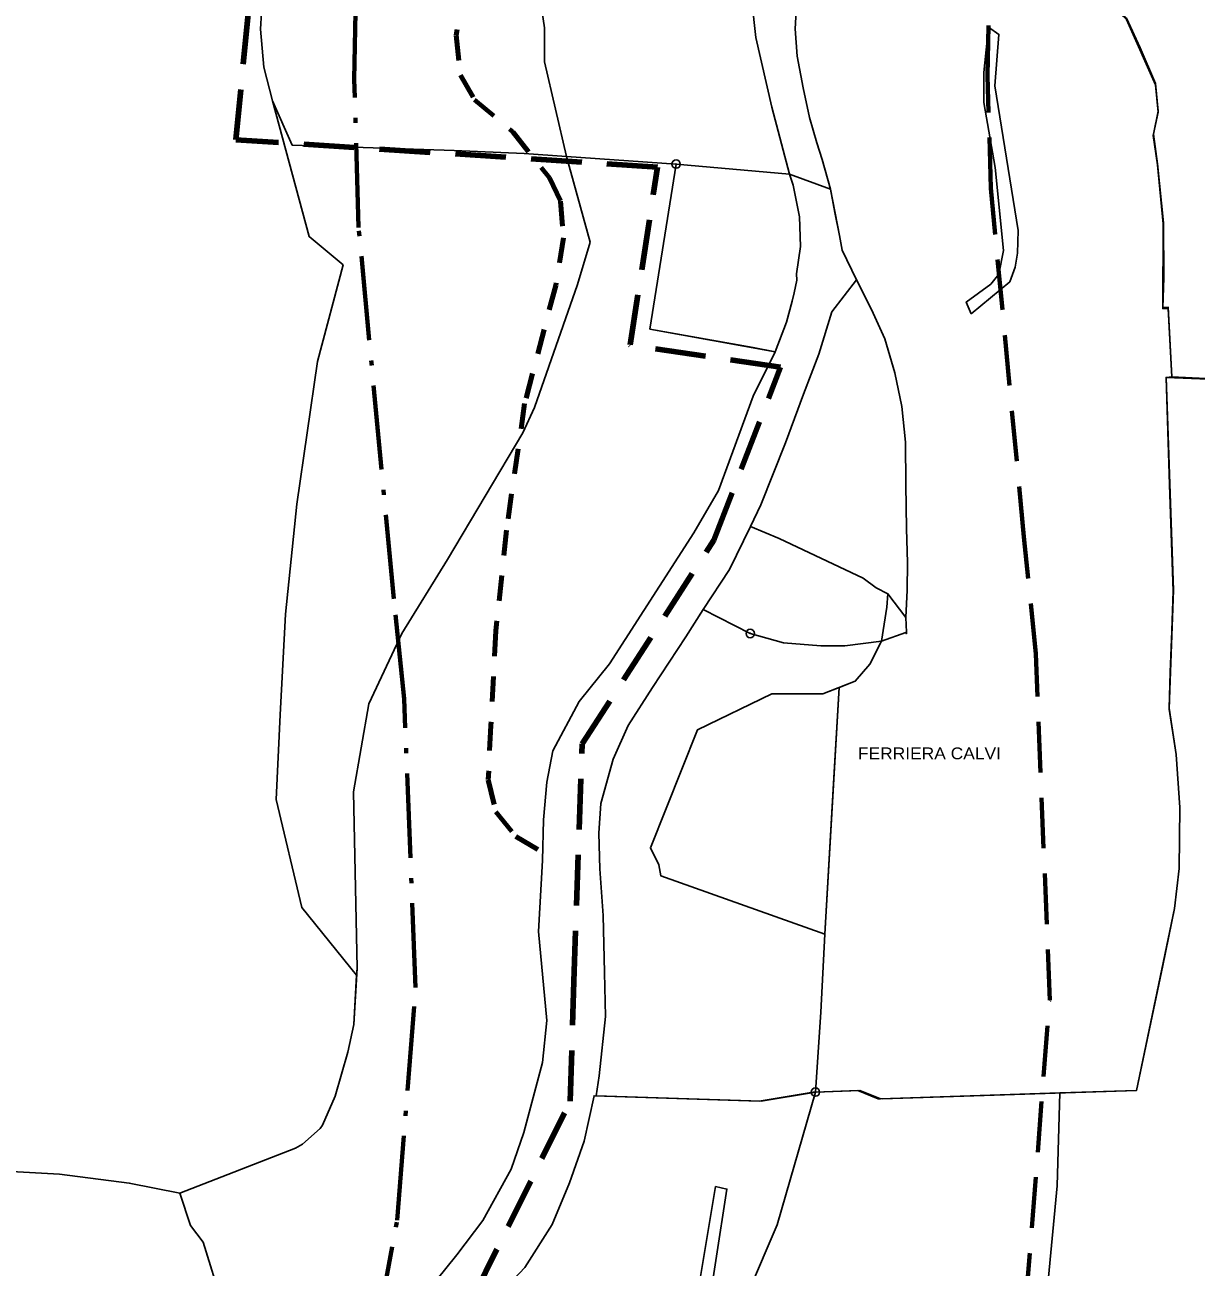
# Model space of a CAD drawing. Extents: x 654952 to 658955, y 890426 to 894481.
# Drawn here: x 658035.3 to 658312.8, y 893224.6 to 893519 of the extents above; entities that cross this region are included whole.
import ezdxf

# ---------------------------------------------------------------- set-up
doc = ezdxf.new("R2010")
doc.units = 0
doc.header["$LTSCALE"] = 4
doc.header["$PDMODE"] = 32
doc.header["$PDSIZE"] = 2
for name, pattern in [('DOT_DASHED', [7.7, 5, -1.2, 0.3, -1.2]), ('MEDIUM_DASHED', [4.5, 3, -1.5]), ('SHORT_DASHED', [2.7, 1.5, -1.2])]:
    doc.linetypes.add(name, pattern=pattern)
for name, color, linetype, lineweight in [('1', 7, 'Continuous', 25), ('18', 7, 'Continuous', 25), ('19', 7, 'Continuous', 25), ('23', 7, 'Continuous', 25), ('29', 7, 'Continuous', 25), ('31', 7, 'Continuous', 25), ('35', 7, 'Continuous', 25), ('41', 7, 'SHORT_DASHED', 80), ('42', 7, 'Continuous', 25), ('43', 7, 'Continuous', 25), ('45', 7, 'Continuous', 25), ('55', 7, 'Continuous', 25), ('57', 7, 'Continuous', 25), ('7', 7, 'MEDIUM_DASHED', 100), ('9', 7, 'Continuous', 25)]:
    doc.layers.add(name, color=color, linetype=linetype, lineweight=lineweight)
doc.layers.add('58', color=7, linetype='Continuous')

msp = doc.modelspace()

# ---------------------------------------------------------------- linework, layer by layer
at = {"layer": '1'}
msp.add_line((658224.78, 893303.49), (658228.2, 893361.92), dxfattribs=at)
msp.add_lwpolyline([(658228.2, 893361.92), (658224.37, 893360.42), (658212.25, 893360.42), (658194.63, 893351.92), (658183.5, 893323.92), (658185.5, 893319.92), (658185.93, 893317.32), (658224.78, 893303.49)], dxfattribs=at)
at = {"layer": '18'}
for points in [[(658238.25, 893372.92), (658239.5, 893380.92), (658239.72, 893384.12), (658236.93, 893385.56), (658233.87, 893387.81), (658213.99, 893397.25), (658207.16, 893400.06), (658202.25, 893389.92), (658196, 893380.42), (658207.14, 893374.72)], [(658207.14, 893374.72), (658214.98, 893372.47), (658223.86, 893371.79), (658229.56, 893371.79), (658238.25, 893372.92)]]:
    msp.add_lwpolyline(points, dxfattribs=at)
at = {"layer": '19'}
msp.add_line((658207.14, 893374.72), (658196, 893380.42), dxfattribs=at)
for points in [[(658196, 893380.42), (658191.87, 893373.92), (658184, 893361.92), (658178.25, 893352.92), (658174.63, 893344.92), (658171.75, 893334.42), (658171.25, 893327.42), (658171.5, 893318.92), (658172.25, 893307.92), (658172.63, 893294.42), (658172.87, 893283.92), (658171.37, 893269.92), (658170.65, 893265.17), (658209.75, 893263.92), (658222.58, 893266.04)], [(658238.25, 893372.92), (658229.56, 893371.79), (658223.86, 893371.79), (658214.98, 893372.47), (658207.14, 893374.72)], [(658212.25, 893360.42), (658224.37, 893360.42), (658232, 893363.42), (658235.5, 893367.42), (658238.25, 893372.92)], [(658222.58, 893266.04), (658223.87, 893284.97), (658224.78, 893303.49), (658185.93, 893317.32), (658185.5, 893319.92), (658183.5, 893323.92), (658194.63, 893351.92), (658212.25, 893360.42)]]:
    msp.add_lwpolyline(points, dxfattribs=at)
for p in [(658207.14, 893374.72), (658222.58, 893266.04)]:
    msp.add_point(p, dxfattribs=at)
at = {"layer": '23'}
msp.add_line((658239.72, 893384.12), (658244.02, 893378.52), dxfattribs=at)
for points in [[(658228.02, 893561.02), (658227.4, 893561.52), (658223.52, 893552.02), (658220.28, 893541.52), (658219.15, 893534.52), (658218.28, 893526.52), (658217.78, 893518.02), (658218.28, 893511.52), (658219.65, 893504.02), (658221.15, 893497.02), (658222.9, 893491.02), (658224.15, 893487.02), (658226.15, 893480.02), (658227.15, 893474.52), (658228.28, 893469.02), (658228.89, 893465.55)], [(658304.9, 893451.96), (658305.15, 893459.02), (658305.02, 893472.02), (658303.65, 893486.02), (658302.65, 893493.02), (658303.78, 893498.52), (658303.15, 893505.02), (658299.52, 893513.52), (658296.28, 893520.52), (658292.02, 893524.52), (658288.28, 893526.02), (658282.9, 893527.52), (658280.46, 893527.27), (658268.49, 893526.19)], [(658228.89, 893465.55), (658232.28, 893458.52), (658235.9, 893451.52), (658239.02, 893444.52), (658241.4, 893436.52)], [(658241.4, 893436.52), (658239.02, 893444.52), (658235.9, 893451.52), (658232.28, 893458.52), (658226.5, 893450.92)], [(658226.5, 893450.92), (658223.37, 893440.92), (658219.75, 893431.42), (658215.5, 893419.92), (658209.65, 893405.22), (658207.16, 893400.06)], [(658237.96, 893264.45), (658298.66, 893266.44), (658307.65, 893309.52), (658308.78, 893319.02), (658308.9, 893333.52), (658308.02, 893346.02), (658306.4, 893357.02), (658306.65, 893365.52), (658307.4, 893385.02), (658305.64, 893435.4), (658307.02, 893435.52), (658306.15, 893452.02), (658304.9, 893451.96)], [(658241.4, 893436.52), (658243.02, 893428.52), (658243.9, 893420.02), (658244.02, 893410.02), (658244.15, 893399.52), (658244.4, 893391.52), (658244.28, 893385.02), (658244.02, 893378.52), (658244.15, 893375.02), (658244.15, 893374.66), (658244, 893374.92), (658238.25, 893372.92), (658235.5, 893367.42), (658232, 893363.42), (658228.2, 893361.92), (658226.79, 893337.79), (658224.78, 893303.49), (658223.87, 893284.97), (658222.58, 893266.04), (658233.13, 893266.42), (658237.96, 893264.45)], [(658244.02, 893378.52), (658244.28, 893385.02), (658244.4, 893391.52), (658244.15, 893399.52), (658244.02, 893410.02), (658243.9, 893420.02), (658243.02, 893428.52), (658241.4, 893436.52)], [(658207.16, 893400.06), (658213.99, 893397.25), (658233.87, 893387.81), (658236.93, 893385.56), (658239.72, 893384.12)]]:
    msp.add_lwpolyline(points, dxfattribs=at)
at = {"layer": '29'}
msp.add_line((658163.63, 893487.74), (658189.57, 893485.96), dxfattribs=at)
for points in [[(658200.64, 893654.32), (658194.38, 893637.81), (658190.34, 893629.07), (658171.5, 893586.66), (658154.38, 893545.32), (658158.38, 893518.26), (658158.38, 893510.16), (658163.63, 893487.74), (658153.61, 893488.43), (658136.98, 893489.18), (658098.61, 893490.43)], [(658200.64, 893654.32), (658194.38, 893637.81), (658190.34, 893629.07), (658171.5, 893586.66), (658154.38, 893545.32), (658158.38, 893518.26), (658158.38, 893510.16), (658163.63, 893487.74)], [(658189.57, 893485.96), (658216.43, 893483.57), (658212.24, 893499.43), (658208.48, 893515.93), (658207.52, 893524.57), (658208.22, 893531.09), (658209.29, 893536.92), (658212.82, 893549.27), (658219.54, 893570.54), (658224.85, 893584.61), (658228.03, 893592.15), (658234.04, 893604.5), (658239.34, 893617.2), (658247.36, 893637.43), (658241.86, 893639.43), (658233.36, 893642.43), (658221.98, 893645.43), (658210.86, 893650.43), (658200.64, 893654.32)], [(658098.61, 893490.43), (658093.98, 893500.93), (658091.86, 893508.93), (658091.11, 893517.93), (658091.61, 893525.93)]]:
    msp.add_lwpolyline(points, dxfattribs=at)
msp.add_point((658189.57, 893485.96), dxfattribs=at)
at = {"layer": '31'}
msp.add_lwpolyline([(658082, 893215.94), (658077.5, 893230.44), (658074.5, 893234.44), (658072.01, 893242.12), (658060.01, 893244.47), (658043.47, 893246.59), (658019.17, 893247.9), (658008.87, 893247.09), (658003.99, 893245.61), (657993.63, 893244.44)], dxfattribs=at)
at = {"layer": '35'}
for points in [[(658048.64, 893668.44), (658067.94, 893652.82), (658084.42, 893640.24), (658090.73, 893629.54), (658088.61, 893620.93), (658085.74, 893613.93), (658081.24, 893602.93), (658078.61, 893591.93), (658078.48, 893583.93), (658079.24, 893577.43), (658080.61, 893575.43), (658082.98, 893575.93), (658086.61, 893574.93), (658093.11, 893572.43), (658096.61, 893569.93), (658097.98, 893567.93), (658098.11, 893564.43), (658097.98, 893558.93), (658096.98, 893551.93), (658091.61, 893525.93), (658091.11, 893517.93), (658091.86, 893508.93), (658093.98, 893500.93)], [(658093.98, 893500.93), (658102.66, 893468.79), (658110.65, 893462.08), (658104.61, 893439.16), (658099.73, 893405.33), (658097.02, 893379.27), (658095.75, 893355.48), (658094.79, 893335.37)], [(658163.63, 893487.74), (658169.21, 893467.42), (658166.2, 893457.42), (658156, 893428.28), (658153.22, 893422.3), (658135.37, 893392.24), (658124.56, 893374.75), (658116.74, 893358.02), (658113.17, 893337.22), (658113.97, 893295.43), (658113.18, 893282.04), (658111.83, 893275.53), (658108.79, 893265.05), (658105.79, 893258.24), (658105.21, 893257.43), (658101.06, 893253.7), (658099.39, 893252.75), (658072.01, 893242.12), (658074.5, 893234.44), (658077.5, 893230.44), (658082, 893215.94), (658084.63, 893208.44), (658084.42, 893206.29), (658086.13, 893199.43)], [(658130.42, 893218.53), (658137.61, 893227.46), (658143.8, 893235.63), (658150.49, 893247.78), (658153.46, 893256.46), (658157.92, 893273.07), (658158.91, 893282.99), (658156.93, 893304.06), (658157.92, 893320.91), (658158.17, 893330.58), (658158.91, 893339.51), (658160.4, 893346.95), (658166.6, 893358.6), (658173.78, 893367.53), (658193.74, 893398.56), (658199.64, 893408.58), (658207.86, 893430.96), (658213.07, 893441.46), (658183.35, 893446.86), (658189.57, 893485.96), (658163.63, 893487.74)], [(658094.79, 893335.37), (658100.88, 893309.75), (658113.87, 893293.75)], [(658113.87, 893293.75), (658113.18, 893282.04), (658111.83, 893275.53), (658108.79, 893265.05), (658105.79, 893258.24), (658105.21, 893257.43), (658101.06, 893253.7), (658099.39, 893252.75), (658072.01, 893242.12)], [(658072.01, 893242.12), (658060.01, 893244.47), (658043.47, 893246.59), (658019.17, 893247.9), (658008.87, 893247.09), (658003.99, 893245.61), (657993.63, 893244.44), (657991.13, 893240.44), (657986.37, 893235.94), (657980.75, 893232.44), (657969.25, 893228.44), (657966, 893227.44), (657963, 893225.44), (657960.13, 893222.44)]]:
    msp.add_lwpolyline(points, dxfattribs=at)
at = {"layer": '41'}
msp.add_lwpolyline([(658163.03, 893644.67), (658167.24, 893634), (658167.97, 893622.73), (658156.34, 893582.35), (658147.61, 893555.79), (658139.61, 893528.5), (658137.43, 893516.5), (658138.52, 893507.04), (658141.79, 893501.22), (658150.88, 893493.58), (658159.61, 893482.67), (658162.16, 893477.21), (658162.88, 893468.47), (658161.06, 893457.2), (658153.69, 893429.19), (658149.36, 893399.18), (658146.89, 893375.35), (658145.68, 893352.95), (658145.07, 893340.06), (658146.89, 893332.42), (658151.61, 893326.6), (658157.79, 893322.96)], dxfattribs=at)
at = {"layer": '42'}
for points in [[(658163.63, 893487.74), (658153.61, 893488.43), (658136.98, 893489.18), (658098.61, 893490.43), (658093.98, 893500.93)], [(658093.98, 893500.93), (658102.66, 893468.79), (658110.65, 893462.08), (658104.61, 893439.16), (658099.73, 893405.33), (658097.02, 893379.27), (658095.75, 893355.48), (658094.79, 893335.37)], [(658113.87, 893293.75), (658113.97, 893295.43), (658113.17, 893337.22), (658116.74, 893358.02), (658124.56, 893374.75), (658135.37, 893392.24), (658153.22, 893422.3), (658156, 893428.28), (658166.2, 893457.42), (658169.21, 893467.42), (658163.63, 893487.74)], [(658094.79, 893335.37), (658100.88, 893309.75), (658113.87, 893293.75)]]:
    msp.add_lwpolyline(points, dxfattribs=at)
at = {"layer": '43'}
msp.add_line((658222.58, 893266.04), (658232.66, 893266.4), dxfattribs=at)
for points in [[(658352.42, 893869.89), (658400.68, 893840.76), (658358.48, 893763.16), (658343.9, 893727.46), (658322.5, 893619.12), (658323.74, 893553.3), (658329.32, 893488.12), (658329.63, 893434.42), (658307.02, 893435.52), (658306.12, 893451.76), (658304.87, 893451.7), (658305, 893471.76), (658303.62, 893485.76), (658302.62, 893492.76), (658303.75, 893498.26), (658303.12, 893504.76), (658296.25, 893520.26), (658292, 893524.26), (658287.7, 893525.94), (658282.87, 893527.26), (658268.47, 893525.98)], [(658329.63, 893434.42), (658305.64, 893435.4), (658306.49, 893409.95), (658307.37, 893384.76), (658306.37, 893356.76), (658308.02, 893346.02), (658308.9, 893333.52), (658308.78, 893319.02), (658307.65, 893309.52), (658304.89, 893296.03), (658298.66, 893266.44), (658238.47, 893264.47)], [(658222.58, 893266.06), (658222.07, 893266.04), (658209.24, 893263.92), (658170.14, 893265.17), (658170.14, 893265.17), (658167.76, 893254.43), (658164.28, 893244.53), (658160.18, 893234.63), (658153.76, 893224.46), (658143.12, 893213.23), (658147.76, 893207.45)], [(658198.48, 893201.41), (658200.15, 893203.39), (658213.49, 893234.6), (658222.58, 893266.04)], [(658237.96, 893264.45), (658237.45, 893264.45), (658232.66, 893266.4), (658222.58, 893266.04), (658213.49, 893234.6)], [(658232.66, 893266.4), (658232.62, 893266.42), (658222.58, 893266.06), (658222.58, 893266.04)], [(658271.84, 893188.89), (658274.85, 893203.3), (658277.65, 893220.56), (658279.85, 893243.85), (658280.46, 893265.84), (658237.96, 893264.45)], [(658238.47, 893264.47), (658238.47, 893264.45), (658280.46, 893265.84)], [(658280.46, 893265.84), (658279.85, 893243.85), (658277.65, 893220.56), (658274.85, 893203.3), (658271.84, 893188.89)], [(658213.49, 893234.6), (658200.15, 893203.39), (658198.48, 893201.42), (658201.75, 893200.44), (658201.13, 893198.45)]]:
    msp.add_lwpolyline(points, dxfattribs=at)
at = {"layer": '45', "linetype": 'DOT_DASHED', "lineweight": 70}
msp.add_lwpolyline([(657888.75, 892244.36), (657949.53, 892498.78), (657993.28, 892680.38), (658112.95, 893179.41), (658123.49, 893235.71), (658127.84, 893290.79), (658125.12, 893359.25), (658122.7, 893382.9), (658114.35, 893470.93), (658113.32, 893505.97), (658113.89, 893537.78), (658115.35, 893563.44), (658117.94, 893594.58), (658121.29, 893618.7), (658125.97, 893646.13), (658131.56, 893672.78), (658136.29, 893692.48), (658143.9, 893719.95), (658153.86, 893751.08), (658170.87, 893795.19), (658185.72, 893828.64), (658194.88, 893846.97), (658209.57, 893874.93), (658233.56, 893914.96)], dxfattribs=at)
at = {"layer": '45', "linetype": 'MEDIUM_DASHED', "lineweight": 70}
msp.add_lwpolyline([(658035.6, 892213.52), (658095.39, 892463.77), (658139.14, 892645.31), (658259.68, 893148.09), (658272.39, 893215.94), (658278.08, 893287.85), (658274.82, 893369.87), (658271.98, 893397.63), (658264.14, 893480.23), (658263.35, 893506.84), (658263.8, 893532.17), (658264.99, 893552.95), (658267.07, 893578), (658269.55, 893595.75), (658273.36, 893618.11), (658277.93, 893639.87), (658281.55, 893654.95), (658287.66, 893677.05), (658295.4, 893701.19), (658309.47, 893737.74), (658321.42, 893764.63), (658328.38, 893778.55), (658340.4, 893801.43), (658362.23, 893837.86)], dxfattribs=at)
at = {"layer": '55'}
msp.add_line((658216.43, 893483.57), (658226.15, 893480.02), dxfattribs=at)
for points in [[(658222.32, 893678.87), (658221.89, 893667.62), (658221.45, 893656.37), (658222.07, 893651.87), (658221.95, 893645.37), (658210.86, 893650.43), (658200.64, 893654.32), (658194.38, 893637.81), (658190.34, 893629.07), (658171.5, 893586.66), (658154.38, 893545.32), (658158.38, 893518.26), (658158.38, 893510.16), (658163.63, 893487.74), (658189.57, 893485.96)], [(658226.15, 893480.02), (658224.15, 893487.02), (658222.9, 893491.02), (658221.15, 893497.02), (658219.65, 893504.02), (658218.28, 893511.52), (658217.78, 893518.02), (658218.28, 893526.52), (658219.15, 893534.52), (658220.28, 893541.52), (658223.52, 893552.02), (658227.4, 893561.52), (658228.02, 893561.02), (658233.77, 893554.25), (658237.02, 893557.02)], [(658296.28, 893520.52), (658299.52, 893513.52), (658303.15, 893505.02), (658303.78, 893498.52), (658302.65, 893493.02), (658303.65, 893486.02), (658305.02, 893472.02), (658305.15, 893459.02), (658304.9, 893451.96), (658306.15, 893452.02), (658307.02, 893435.52), (658305.64, 893435.4), (658307.4, 893385.02), (658306.4, 893357.02), (658308.02, 893346.02), (658308.9, 893333.52), (658308.78, 893319.02), (658307.65, 893309.52), (658298.66, 893266.44), (658280.46, 893265.84)], [(658163.63, 893487.74), (658169.21, 893467.42), (658166.2, 893457.42), (658156, 893428.28), (658153.22, 893422.3), (658135.37, 893392.24), (658124.56, 893374.75), (658116.74, 893358.02), (658113.17, 893337.22), (658113.97, 893295.43), (658113.18, 893282.04), (658111.83, 893275.53), (658108.79, 893265.05), (658105.79, 893258.24), (658105.21, 893257.43), (658101.06, 893253.7), (658099.39, 893252.75), (658072.01, 893242.12), (658074.5, 893234.44), (658077.5, 893230.44), (658082, 893215.94)], [(658216.43, 893483.57), (658189.57, 893485.96), (658163.63, 893487.74)], [(658189.57, 893485.96), (658216.43, 893483.57), (658226.15, 893480.02)], [(658228.89, 893465.55), (658228.28, 893469.02), (658226.15, 893480.02), (658216.43, 893483.57)], [(658209.65, 893405.22), (658215.5, 893419.92), (658219.75, 893431.42), (658223.37, 893440.92), (658226.5, 893450.92), (658232.28, 893458.52), (658228.89, 893465.55)], [(658239.72, 893384.12), (658236.93, 893385.56), (658233.87, 893387.81), (658213.99, 893397.25), (658207.16, 893400.06), (658209.65, 893405.22)], [(658198.48, 893201.41), (658200.15, 893203.39), (658213.49, 893234.6), (658222.58, 893266.04), (658223.87, 893284.97), (658224.78, 893303.49), (658226.74, 893337.73), (658226.79, 893337.79), (658228.2, 893361.92), (658232, 893363.42), (658235.5, 893367.42), (658238.25, 893372.92), (658244, 893374.92), (658244.15, 893374.66), (658244.15, 893375.02), (658244.02, 893378.52), (658239.72, 893384.12)], [(658280.46, 893265.84), (658279.85, 893243.85), (658277.65, 893220.56), (658274.85, 893203.3), (658271.84, 893188.89), (658271.83, 893188.84)]]:
    msp.add_lwpolyline(points, dxfattribs=at)
msp.add_point((658189.57, 893485.96), dxfattribs=at)
at = {"layer": '57'}
for points in [[(658263.55, 893518.44), (658262.49, 893507.69), (658262.49, 893500.56), (658265.18, 893485.13), (658267.12, 893465.5), (658266.05, 893459.87), (658264.12, 893457.5), (658258.31, 893453.25), (658259.51, 893450.5)], [(658259.51, 893450.5), (658268.62, 893458.06), (658269.93, 893461.5), (658270.43, 893464.81), (658270.62, 893470.25), (658265.12, 893504.5), (658266.05, 893516.69), (658263.55, 893518.44)]]:
    msp.add_lwpolyline(points, dxfattribs=at)
msp.add_lwpolyline([(658180.08, 893173.37), (658183.87, 893186.5), (658196.37, 893209.19), (658201.62, 893243.06), (658198.93, 893243.63), (658193.31, 893210), (658181.43, 893188.37), (658176.95, 893174.37)], close=True, dxfattribs=at)
at = {"layer": '7'}
msp.add_lwpolyline([(658141.8, 893218.08), (658164.49, 893263.9), (658165.31, 893292.28), (658167.33, 893348.61), (658198.53, 893396.86), (658214.34, 893437.82), (658178.68, 893443.09), (658185.17, 893485.26), (658085.26, 893491.71), (658092.37, 893565.14), (658068.06, 893576.49), (658075.76, 893610.95), (658087.91, 893632.85), (658115.06, 893624.33), (658164.09, 893649.07), (658200.96, 893659.61), (658212.72, 893655.96), (658213.93, 893685.96)], dxfattribs=at)
at = {"layer": '9'}
for points in [[(658207.82, 893442.46), (658183.35, 893446.86), (658189.57, 893485.96), (658216.43, 893483.57)], [(658216.43, 893483.57), (658217.32, 893480.96), (658218.82, 893473.46), (658219.07, 893466.46), (658218.07, 893459.96), (658218.19, 893458.46)], [(658218.19, 893458.46), (658217.57, 893455.46), (658217.07, 893453.46), (658215.69, 893448.46), (658213.07, 893441.46), (658207.82, 893442.46)]]:
    msp.add_lwpolyline(points, dxfattribs=at)

# ---------------------------------------------------------------- texts
at = {"layer": '58', "width": 1.1}
msp.add_text('FERRIERA CALVI', height=2.801, dxfattribs=at).set_placement((658232.64, 893344.91))

doc.saveas('drawing.dxf')
